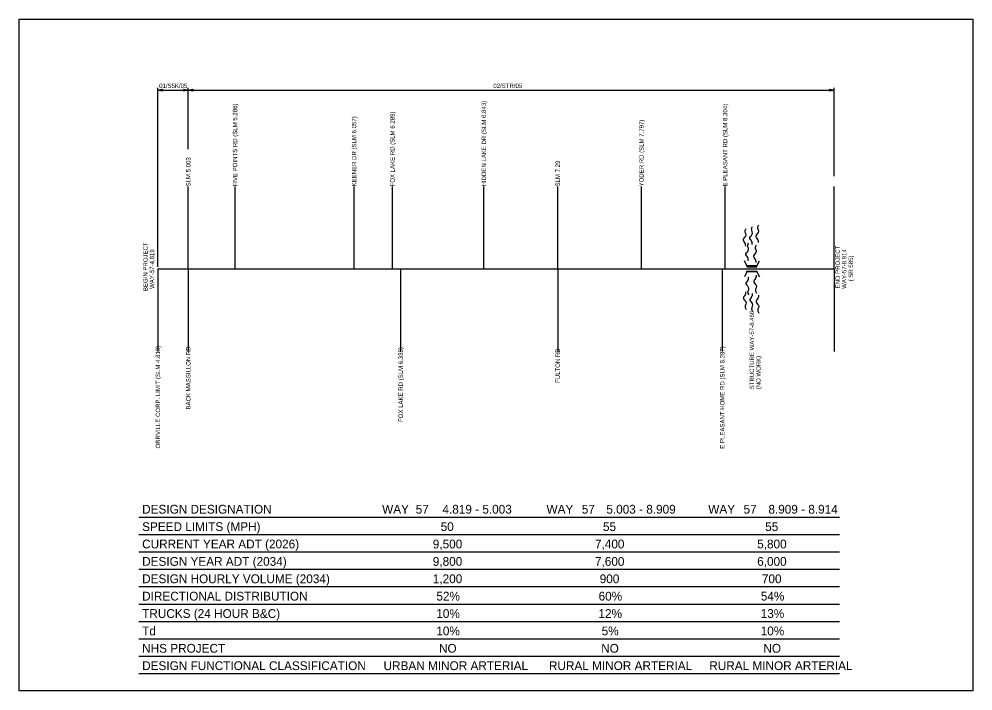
# Model space of a CAD drawing. Extents: x 53469 to 83969, y -33244 to -11744.
import ezdxf

# ---------------------------------------------------------------- set-up
doc = ezdxf.new("R2010")
doc.units = 0
for name, color, linetype in [('Default', 7, 'Continuous'), ('DR_Channel', 7, 'Continuous'), ('GM_X_Corporation', 7, 'Continuous'), ('SC_Scratch1', 7, 'Continuous'), ('SH_Data', 7, 'Continuous'), ('SH_Text', 7, 'Continuous')]:
    doc.layers.add(name, color=color, linetype=linetype)

msp = doc.modelspace()

# ---------------------------------------------------------------- linework, layer by layer
at = {"layer": 'Default'}
for p, q in [((57293, -27682), (79707, -27682)), ((57293, -28238), (79707, -28238)), ((57293, -28795), (79707, -28795)), ((57293, -29351), (79707, -29351)), ((57293, -29907), (79707, -29907)), ((57293, -30463), (79707, -30463)), ((57293, -31019), (79707, -31019)), ((57293, -31576), (79707, -31576)), ((57293, -32132), (79707, -32132)), ((57293, -32688), (79707, -32688))]:
    msp.add_line(p, q, dxfattribs=at)
at = {"layer": 'DR_Channel'}
for points in [[(76702, -19012), (76703, -18999), (76708, -18904), (76571, -18801), (76786, -18658), (76642, -18538), (76714, -18443)], [(76912, -18954), (76913, -18940), (76918, -18845), (76781, -18743), (76996, -18599), (76852, -18480), (76924, -18384)], [(77108, -18897), (77109, -18883), (77114, -18788), (76977, -18685), (77192, -18542), (77048, -18423), (77120, -18327)], [(76786, -19478), (76787, -19464), (76791, -19369), (76654, -19267), (76869, -19123), (76726, -19004), (76798, -18908)], [(77034, -19537), (77035, -19523), (77040, -19428), (76903, -19326), (77118, -19182), (76975, -19063), (77046, -18967)], [(76786, -20001), (76787, -20015), (76791, -20110), (76654, -20212), (76869, -20356), (76726, -20475), (76798, -20571)], [(77034, -19942), (77035, -19956), (77040, -20051), (76903, -20154), (77118, -20297), (76975, -20416), (77046, -20512)], [(76702, -20467), (76703, -20480), (76708, -20575), (76571, -20678), (76786, -20821), (76642, -20941), (76714, -21036)], [(76912, -20525), (76913, -20539), (76918, -20634), (76781, -20736), (76996, -20880), (76852, -20999), (76924, -21095)], [(77108, -20582), (77109, -20596), (77114, -20691), (76977, -20794), (77192, -20937), (77048, -21057), (77120, -21152)]]:
    msp.add_open_spline(points, degree=3, dxfattribs=at)
at = {"layer": 'GM_X_Corporation'}
msp.add_line((57908, -19740), (57908, -22380), dxfattribs=at)
at = {"layer": 'SC_Scratch1'}
msp.add_lwpolyline([(53469, -11744), (83969, -11744), (83969, -33244), (53469, -33244)], close=True, dxfattribs=at)
at = {"layer": 'SH_Data'}
for p, q in [((58880, -19740), (58880, -17100)), ((60374, -19740), (60374, -17100)), ((64181, -19740), (64181, -17100)), ((65406, -19740), (65406, -17100)), ((68331, -19740), (68331, -17100)), ((70691, -19740), (70691, -17100)), ((73368, -19740), (73368, -17100)), ((76045, -19740), (76045, -17100)), ((79530, -19740), (79530, -17100)), ((76740, -19644), (76660, -19484)), ((77060, -19644), (77140, -19484)), ((57908, -19740), (79530, -19740)), ((58880, -19740), (58880, -22380)), ((65670, -19740), (65670, -22380)), ((70691, -19740), (70691, -22380)), ((75955, -19740), (75955, -22380)), ((77060, -19644), (76740, -19644)), ((76740, -19644), (76740, -19669)), ((76740, -19669), (77060, -19669)), ((76740, -19835), (76740, -19810)), ((76740, -19810), (77060, -19810)), ((77060, -19669), (77060, -19644)), ((77060, -19810), (77060, -19835)), ((79530, -19740), (79530, -22380)), ((76740, -19835), (76660, -19995)), ((77060, -19835), (76740, -19835)), ((77060, -19835), (77140, -19995))]:
    msp.add_line(p, q, dxfattribs=at)
at = {"layer": 'SH_Text'}
for p, q in [((57908, -19670), (57908, -13950)), ((57908, -14020), (58880, -14020)), ((58880, -15905), (58880, -13950)), ((58880, -14020), (79530, -14020)), ((79530, -16768), (79530, -13950))]:
    msp.add_line(p, q, dxfattribs=at)
for points in [[(58048, -14048), (57908, -14020), (58048, -13992)], [(58740, -13992), (58880, -14020), (58740, -14048)], [(59020, -14048), (58880, -14020), (59020, -13992)], [(79390, -13992), (79530, -14020), (79390, -14048)]]:
    msp.add_lwpolyline(points, close=True, dxfattribs=at)

# ---------------------------------------------------------------- texts
at = {"layer": 'Default'}
for s, height, p in [('DESIGN DESIGNATION', 281.43, (57404, -27571)), ('WAY', 281.4, (65078, -27571)), ('57', 281.4, (66151, -27571)), ('4.819 - 5.003', 281.43, (67006, -27571)), ('WAY', 281.4, (70334, -27571)), ('57', 281.4, (71462, -27571)), ('5.003 - 8.909', 281.43, (72247, -27571)), ('WAY', 281.4, (75506, -27571)), ('57', 281.4, (76635, -27571)), ('8.909 - 8.914', 281.43, (77429, -27571)), ('SPEED LIMITS (MPH)', 281.43, (57404, -28127)), ('50', 281.4, (66950, -28127)), ('55', 281.4, (72140, -28127)), ('55', 281.4, (77326, -28127)), ('CURRENT YEAR ADT (2026)', 281.43, (57404, -28683)), ('9,500', 281.4, (66698, -28683)), ('7,400', 281.4, (71884, -28683)), ('5,800', 281.4, (77071, -28683)), ('DESIGN YEAR ADT (2034)', 281.43, (57404, -29240)), ('9,800', 281.4, (66698, -29240)), ('7,600', 281.4, (71884, -29240)), ('6,000', 281.4, (77071, -29240)), ('DESIGN HOURLY VOLUME (2034)', 281.43, (57404, -29796)), ('1,200', 281.4, (66698, -29796)), ('900', 281.4, (72035, -29796)), ('700', 281.4, (77221, -29796)), ('DIRECTIONAL DISTRIBUTION', 281.43, (57404, -30352)), ('52%', 281.4, (66813, -30352)), ('60%', 281.4, (72000, -30352)), ('54%', 281.4, (77186, -30352)), ('TRUCKS (24 HOUR B&C)', 281.43, (57404, -30908)), ('10%', 281.4, (66810, -30908)), ('12%', 281.4, (71996, -30908)), ('13%', 281.4, (77183, -30908)), ('Td', 281.4, (57404, -31464)), ('10%', 281.4, (66810, -31464)), ('5%', 281.4, (72097, -31464)), ('10%', 281.4, (77183, -31464)), ('NHS PROJECT', 281.43, (57404, -32021)), ('NO', 281.4, (66896, -32021)), ('NO', 281.4, (72083, -32021)), ('NO', 281.4, (77269, -32021)), ('DESIGN FUNCTIONAL CLASSIFICATION', 281.43, (57404, -32577)), ('URBAN MINOR ARTERIAL', 281.43, (65123, -32577)), (' RURAL MINOR ARTERIAL', 281.43, (70307, -32577)), ('RURAL MINOR ARTERIAL', 281.43, (75539, -32577))]:
    msp.add_text(s, height=height, dxfattribs=at).set_placement(p)
at = {"layer": 'SH_Text'}
for s, p in [('01/S5K/05', (57947, -13949)), ('02/STR/05', (68633, -13949))]:
    msp.add_text(s, height=140, dxfattribs=at).set_placement(p)
for s, p in [('FIVE POINTS RD (SLM 5.286)', (60444, -17100)), ('HIDDEN LAKE DR (SLM 6.843)', (68401, -17100)), ('E PLEASANT RD (SLM 8.304)', (76115, -17100)), ('KEENER DR (SLM 6.057)', (64251, -17100)), ('FOX LAKE RD (SLM 6.289)', (65476, -17100)), ('YODER RD (SLM 7.797)', (73438, -17100)), ('SLM 5.003', (58950, -17100)), ('SLM 7.29', (70761, -17100)), ('BEGIN PROJECT', (57579, -20449)), ('WAY-57-4.819', (57789, -20380)), ('END PROJECT', (79713, -20361)), ('WAY-57-8.914', (79923, -20377)), ('( SR 585)', (80133, -20139)), ('STRUCTURE WAY-57-8.466', (76970, -23591)), ('ORRVILLE CORP. LIMIT (SLM 4.819)', (57978, -25486)), ('BACK MASSILLON RD', (58950, -24237)), ('FOX LAKE RD (SLM 6.339)', (65740, -24637)), ('FULTON RD', (70761, -23388)), ('E PLEASANT HOME RD (SLM 8.287)', (76025, -25493)), ('(NO WORK)', (77180, -23591))]:
    msp.add_text(s, height=140, rotation=90, dxfattribs=at).set_placement(p)

doc.saveas('drawing.dxf')
